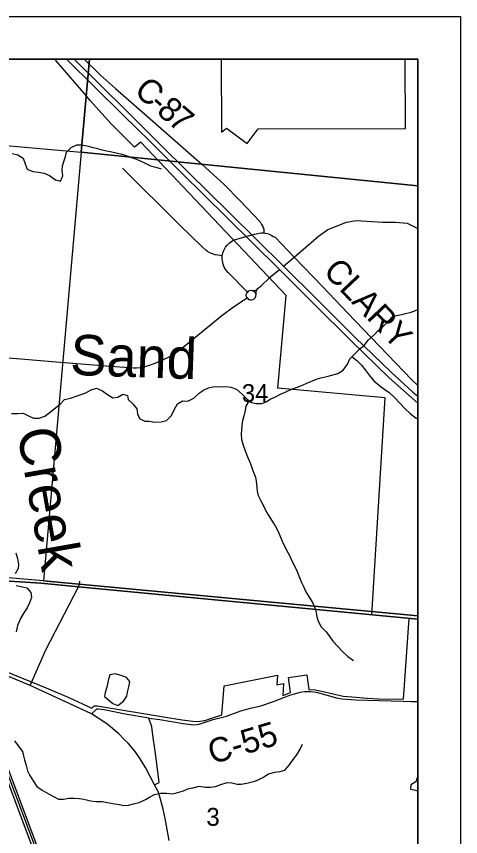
# Model space of a CAD drawing. Extents: x 0 to 34, y 0 to 22.
# Drawn here: x 29.378 to 30.417, y 19.082 to 21 of the extents above; entities that cross this region are included whole.
import ezdxf

# ---------------------------------------------------------------- set-up
doc = ezdxf.new("R2010")
doc.units = 0
for name, color, linetype in [('GM_X_City_Street', 7, 'Continuous'), ('GM_X_Corporation', 7, 'Continuous'), ('GM_X_County_Road', 7, 'Continuous'), ('GM_X_County_Road_Text', 7, 'Continuous'), ('GM_X_Major_River', 7, 'Continuous'), ('GM_X_Major_River_Text', 7, 'Continuous'), ('GM_X_Minor_Lake', 7, 'Continuous'), ('GM_X_Minor_River', 7, 'Continuous'), ('GM_X_Minor_River_Text', 7, 'Continuous'), ('GM_X_Rail_Line', 7, 'Continuous'), ('GM_X_Section_Text', 7, 'Continuous'), ('GM_X_State_Route', 7, 'Continuous'), ('GM_X_Township_Road', 7, 'Continuous'), ('GM_X_US_Route', 7, 'Continuous'), ('SH_Data', 7, 'Continuous')]:
    doc.layers.add(name, color=color, linetype=linetype)

msp = doc.modelspace()

# ---------------------------------------------------------------- linework, layer by layer
at = {"layer": 'GM_X_City_Street'}
for points in [[(29.8594, 20.44), (29.8487, 20.4415), (29.8428, 20.4426), (29.8363, 20.4448), (29.8299, 20.4469), (29.8248, 20.4502), (29.8206, 20.4536), (29.812, 20.4612), (29.7604, 20.5117), (29.6261, 20.645)], [(29.9382, 20.3499), (29.937, 20.3526), (29.9356, 20.3546), (29.9343, 20.3563), (29.9301, 20.358), (29.9275, 20.3588), (29.923, 20.3583), (29.9197, 20.3573), (29.9179, 20.3553), (29.873, 20.4009), (29.8673, 20.4073), (29.8639, 20.414), (29.8614, 20.421), (29.8595, 20.4288), (29.8592, 20.4334), (29.8594, 20.44)], [(29.9177, 20.3417), (29.9162, 20.3446), (29.9154, 20.3476), (29.9154, 20.3501), (29.9166, 20.3529), (29.9179, 20.3553)], [(29.9177, 20.3417), (29.921, 20.3384), (29.9243, 20.3371), (29.9274, 20.3371), (29.931, 20.3378), (29.9341, 20.3393), (29.9364, 20.3421), (29.9377, 20.3458), (29.9382, 20.3499)], [(28.95, 20.2316), (29.0526, 20.2256), (29.1647, 20.2167), (29.2757, 20.2079), (29.3882, 20.1992), (29.48, 20.1917), (29.5875, 20.1831), (29.6516, 20.1783), (29.6584, 20.1781), (29.6681, 20.179), (29.6791, 20.1815), (29.6912, 20.1852), (29.7063, 20.1906), (29.722, 20.1978), (29.7365, 20.205), (29.7592, 20.2196), (29.858, 20.3004), (29.8857, 20.3208), (29.9177, 20.3417)]]:
    msp.add_lwpolyline(points, dxfattribs=at)
at = {"layer": 'GM_X_Corporation'}
for points in [[(27.713, 19.8126), (27.7479, 19.8098), (27.921, 19.7976), (28.0078, 19.7898), (28.15, 19.7813), (28.3845, 19.7702), (28.4743, 19.7657), (28.6835, 19.7478), (28.7311, 19.743), (28.8977, 19.7297), (28.9889, 19.7198), (29.3495, 19.6807), (29.4353, 19.675), (29.5232, 19.6666), (30.3167, 19.5906), (30.3167, 20.9), (26.3743, 20.9)], [(29.5806, 18.6469), (29.2591, 19.5062), (29.4529, 19.4276), (29.5007, 19.4078), (29.5541, 19.3823), (29.5597, 19.3879), (29.5664, 19.3884), (29.731, 19.3604), (29.7656, 19.3552), (29.7905, 19.3521), (29.8008, 19.3516), (29.8187, 19.354), (29.8585, 19.3674), (29.8636, 19.4347), (29.9887, 19.4598), (29.9872, 19.4371), (30.0026, 19.4402), (30.001, 19.4124), (30.0189, 19.419), (30.0139, 19.4545), (30.0571, 19.4606), (30.0619, 19.4264), (30.0769, 19.4252), (30.0952, 19.4213), (30.1144, 19.4168), (30.142, 19.411), (30.1621, 19.4088), (30.1987, 19.4063), (30.2247, 19.4047), (30.2833, 19.4038), (30.2961, 19.5924), (30.2089, 19.6008), (30.2405, 20.1082), (29.9891, 20.1305), (30.0087, 20.3472), (29.6686, 20.7058), (29.6541, 20.6939), (29.6372, 20.7116), (29.5983, 20.7499), (29.5502, 20.8033), (29.5299, 20.8277), (29.4707, 20.8964), (29.467, 20.9), (29.0005, 20.9)], [(30.3167, 14.1), (30.3167, 19.5906), (29.5232, 19.6666), (29.4353, 19.675), (29.3495, 19.6807), (28.9889, 19.7198), (28.8977, 19.7297), (28.7311, 19.743), (28.6835, 19.7478), (28.4743, 19.7657), (28.3845, 19.7702), (28.15, 19.7813), (28.0078, 19.7898), (27.921, 19.7976), (27.7479, 19.8098), (27.713, 19.8126)], [(29.2436, 19.5128), (29.5681, 18.6478)]]:
    msp.add_lwpolyline(points, dxfattribs=at)
for points in [[(29.5485, 20.9), (28.5537, 20.9), (28.5465, 20.7695), (29.5293, 20.6826)], [(30.3167, 20.6035), (30.3167, 20.9), (29.5485, 20.9), (29.5293, 20.6826)], [(30.2871, 20.9), (29.857, 20.9), (29.8577, 20.7293), (29.8692, 20.7387), (29.9178, 20.7025), (29.9435, 20.737), (30.2878, 20.7383)], [(28.5465, 20.7695), (29.5293, 20.6826), (29.4415, 19.6802), (29.3585, 19.6871), (28.4917, 19.7627)], [(30.3167, 19.5984), (30.3167, 20.6035), (29.5293, 20.6826), (29.4415, 19.6802)], [(30.3167, 18.7853), (30.3167, 19.5984), (29.4415, 19.6802), (29.3585, 19.6871), (29.2972, 18.6715), (30.2969, 18.5954)]]:
    msp.add_lwpolyline(points, close=True, dxfattribs=at)
at = {"layer": 'GM_X_County_Road'}
for points in [[(29.5366, 20.9), (29.5747, 20.8628), (29.6097, 20.8311), (29.6843, 20.7659), (29.8124, 20.6539), (29.864, 20.607), (29.9002, 20.5693)], [(29.9002, 20.5693), (29.9476, 20.52), (29.9498, 20.5166), (29.9513, 20.5138), (29.9528, 20.5111), (29.9539, 20.5085), (29.9553, 20.5051), (29.9562, 20.5023), (29.9568, 20.4979), (29.9563, 20.4936)], [(30.1029, 20.4992), (30.1062, 20.5014), (30.1237, 20.5088), (30.1497, 20.519), (30.1728, 20.5227), (30.2349, 20.519), (30.2643, 20.5192), (30.2914, 20.5162), (30.3167, 20.5038)], [(29.8858, 20.4766), (29.8879, 20.4777), (29.9143, 20.4855), (29.9289, 20.489), (29.9347, 20.4905)], [(29.9347, 20.4905), (29.9465, 20.4935), (29.9502, 20.4938), (29.9563, 20.4936)], [(29.9563, 20.4936), (29.9591, 20.4934), (29.9653, 20.4922), (29.969, 20.4908), (29.975, 20.4877), (29.9784, 20.4856), (29.9826, 20.4836), (30.0273, 20.437)], [(30.0028, 20.4163), (30.0273, 20.437), (30.0663, 20.4708), (30.084, 20.4864), (30.1029, 20.4992)], [(29.8594, 20.44), (29.8605, 20.4461), (29.8623, 20.4509), (29.8641, 20.4557), (29.8671, 20.4603), (29.8708, 20.4652), (29.8759, 20.4705), (29.882, 20.4747), (29.8858, 20.4766)], [(30.0273, 20.437), (30.0934, 20.3682), (30.1518, 20.3071), (30.3027, 20.1503), (30.3167, 20.1367)], [(29.9686, 20.3878), (29.9693, 20.3884), (29.993, 20.408)], [(29.9382, 20.3499), (29.9382, 20.3534), (29.9389, 20.357), (29.9402, 20.3605), (29.9435, 20.3643), (29.9509, 20.3705), (29.9686, 20.3878)], [(29.9402, 20.3605), (29.9373, 20.3593), (29.9348, 20.3587), (29.9301, 20.358)], [(29.6878, 19.3589), (29.7135, 19.3561), (29.7681, 19.3467), (29.793, 19.3433), (29.8056, 19.345), (29.8382, 19.356), (29.8689, 19.3638), (29.9029, 19.376), (29.9252, 19.3825), (29.9497, 19.388), (29.9792, 19.398), (30.0176, 19.4129), (30.0412, 19.42), (30.0519, 19.4216), (30.0658, 19.4213), (30.0787, 19.4197), (30.1013, 19.4139), (30.1263, 19.4066), (30.1393, 19.4045), (30.1712, 19.4021), (30.2821, 19.3986)], [(30.2821, 19.3986), (30.3021, 19.398), (30.3167, 19.3984)], [(29.6878, 19.3589), (29.632, 19.3687), (29.5827, 19.3787), (29.5687, 19.3806), (29.5653, 19.38), (29.5538, 19.3697)], [(29.7011, 19.2033), (29.7114, 19.2092), (29.7105, 19.2223), (29.7077, 19.2401), (29.7024, 19.2822), (29.6971, 19.3198), (29.6942, 19.3388), (29.6878, 19.3589)]]:
    msp.add_lwpolyline(points, dxfattribs=at)
at = {"layer": 'GM_X_Major_River'}
for points in [[(29.3768, 19.7455), (29.3801, 19.7329), (29.3827, 19.7188), (29.3818, 19.7094), (29.3753, 19.6965)], [(29.377, 19.6696), (29.3883, 19.6672), (29.4023, 19.6641), (29.4117, 19.653), (29.4131, 19.6416), (29.4085, 19.6287), (29.4027, 19.6174), (29.3954, 19.6053), (29.3873, 19.5925), (29.3803, 19.5762), (29.3776, 19.5614)]]:
    msp.add_lwpolyline(points, dxfattribs=at)
at = {"layer": 'GM_X_Minor_Lake'}
for points in [[(29.614, 19.4614), (29.6097, 19.4626), (29.5964, 19.4607), (29.5922, 19.4475), (29.5891, 19.4319), (29.5857, 19.4194), (29.5838, 19.4099)], [(29.5838, 19.4099), (29.6034, 19.3936), (29.6151, 19.3886), (29.6284, 19.3988), (29.636, 19.4109), (29.6379, 19.4204), (29.641, 19.4325), (29.6429, 19.4446), (29.635, 19.4545), (29.6225, 19.4591), (29.614, 19.4614)], [(30.3167, 19.2305), (30.3162, 19.2224), (30.3116, 19.2107), (30.3006, 19.2035), (30.2998, 19.1936), (30.3081, 19.1916)], [(30.3081, 19.1916), (30.3138, 19.1902), (30.3167, 19.189)]]:
    msp.add_lwpolyline(points, dxfattribs=at)
at = {"layer": 'GM_X_Minor_River'}
for points in [[(29.3682, 20.6796), (29.3815, 20.6765), (29.3939, 20.6685), (29.3984, 20.6552), (29.4033, 20.6427), (29.4165, 20.6373), (29.4294, 20.6361), (29.443, 20.6334), (29.4555, 20.6284), (29.4695, 20.6182), (29.4812, 20.6151), (29.4865, 20.6276), (29.4847, 20.6397), (29.4855, 20.6503), (29.4885, 20.6606), (29.4923, 20.6727), (29.495, 20.6822), (29.506, 20.6931), (29.5189, 20.6999), (29.5295, 20.6999), (29.5424, 20.6972), (29.5541, 20.6945), (29.5643, 20.6922), (29.5753, 20.6891), (29.5851, 20.6868), (29.601, 20.6833), (29.6112, 20.681), (29.6241, 20.6776), (29.6343, 20.6749), (29.6441, 20.6707), (29.6543, 20.6676), (29.6656, 20.6634), (29.6789, 20.6569), (29.6913, 20.6508), (29.7042, 20.6477), (29.7167, 20.6435)], [(29.3665, 20.0713), (29.3802, 20.0712), (29.3934, 20.0727), (29.4059, 20.0658), (29.418, 20.0605), (29.4312, 20.0608), (29.4445, 20.0657), (29.454, 20.0721), (29.4665, 20.0823), (29.4798, 20.0933), (29.49, 20.1046), (29.504, 20.1076), (29.5173, 20.1117), (29.5294, 20.1159), (29.54, 20.1196), (29.5525, 20.1268), (29.5654, 20.1305), (29.579, 20.1244), (29.5888, 20.1172), (29.6036, 20.1084), (29.6153, 20.1095), (29.6271, 20.1167), (29.6377, 20.1136), (29.6391, 20.1041), (29.6501, 20.0942), (29.6591, 20.0828), (29.661, 20.0711), (29.6659, 20.0597), (29.6779, 20.0539), (29.6882, 20.0539), (29.7014, 20.0512), (29.7162, 20.0519), (29.729, 20.0549), (29.7404, 20.067), (29.7465, 20.0802), (29.7545, 20.0939), (29.7663, 20.1014), (29.7784, 20.1006), (29.7928, 20.1074), (29.8061, 20.1199), (29.8156, 20.1259), (29.8273, 20.1319), (29.841, 20.1345), (29.8542, 20.1337), (29.8693, 20.1344), (29.8796, 20.1329), (29.8928, 20.1283), (29.9056, 20.1165), (29.9177, 20.1051), (29.9279, 20.0975), (29.9388, 20.0948), (29.9521, 20.0947), (29.9619, 20.0985), (29.9729, 20.1056), (29.9824, 20.1098), (29.9957, 20.1169), (30.0067, 20.1218), (30.0211, 20.1286), (30.0332, 20.1327), (30.0468, 20.138), (30.0567, 20.1425), (30.0794, 20.1516), (30.0897, 20.1546), (30.1037, 20.1579), (30.1158, 20.1613), (30.1294, 20.1647), (30.142, 20.173), (30.1522, 20.1866), (30.1579, 20.1994), (30.1701, 20.2115), (30.1819, 20.2233), (30.1914, 20.2308), (30.2012, 20.2437), (30.2142, 20.2558), (30.224, 20.2656), (30.2335, 20.2728), (30.2438, 20.2837), (30.2563, 20.2977), (30.2665, 20.3007), (30.2783, 20.3033), (30.2881, 20.3056), (30.301, 20.3086), (30.3108, 20.3127), (30.3167, 20.3146)], [(30.1627, 20.2042), (30.1738, 20.1952), (30.1851, 20.1849), (30.1938, 20.1739), (30.2025, 20.161), (30.2134, 20.1481), (30.2274, 20.1366), (30.2394, 20.1275), (30.2493, 20.1206), (30.2617, 20.1088), (30.2749, 20.0955), (30.2874, 20.0826), (30.2987, 20.0712), (30.3126, 20.0609), (30.3167, 20.0604)], [(29.9223, 20.1016), (29.9146, 20.0888), (29.913, 20.0785), (29.91, 20.0653), (29.9069, 20.0551), (29.9054, 20.0433), (29.9046, 20.0334), (29.9038, 20.0232), (29.9041, 20.0107), (29.9079, 19.9978), (29.9127, 19.9841), (29.918, 19.9701), (29.9236, 19.9575), (29.9277, 19.9473), (29.9319, 19.9363), (29.9367, 19.9226), (29.9386, 19.9131), (29.9401, 19.8995), (29.9412, 19.8896), (29.9434, 19.8797), (29.949, 19.8687), (29.9551, 19.8573), (29.9607, 19.8459), (29.9667, 19.8349), (29.9761, 19.8197), (29.9833, 19.8087), (29.9889, 19.7973), (29.9938, 19.7866), (29.9994, 19.773), (30.0066, 19.7582), (30.0126, 19.7468), (30.0178, 19.7365), (30.0231, 19.7255), (30.0295, 19.7122), (30.0348, 19.7019), (30.04, 19.6879), (30.0449, 19.6761), (30.0502, 19.6655), (30.055, 19.6548), (30.0637, 19.64), (30.0712, 19.6279), (30.0765, 19.6157), (30.0787, 19.6062), (30.0806, 19.596), (30.0839, 19.5861), (30.0903, 19.5728), (30.1024, 19.561), (30.1111, 19.5492), (30.1175, 19.539), (30.1307, 19.526), (30.1397, 19.5161), (30.1533, 19.5036), (30.1661, 19.4941)], [(29.3734, 19.3064), (29.3817, 19.2946), (29.3918, 19.2813), (29.3944, 19.2714), (29.3971, 19.2615), (29.4004, 19.2482), (29.4038, 19.2357), (29.4094, 19.2251), (29.417, 19.2125), (29.4252, 19.1992), (29.4384, 19.1909), (29.4543, 19.1813), (29.4645, 19.1764), (29.4766, 19.1702), (29.488, 19.1698), (29.5008, 19.1721), (29.5126, 19.1724), (29.5243, 19.1712), (29.5353, 19.1697), (29.5511, 19.1658), (29.5644, 19.1643), (29.578, 19.1642), (29.5912, 19.1619), (29.6033, 19.1596), (29.6185, 19.1573), (29.6287, 19.1549), (29.6397, 19.156), (29.6514, 19.159), (29.6647, 19.162), (29.6795, 19.1692), (29.6889, 19.1748), (29.7011, 19.1809), (29.7147, 19.1839), (29.7291, 19.1842), (29.7427, 19.1826), (29.7525, 19.1849), (29.7685, 19.1897), (29.7791, 19.1943), (29.7901, 19.1961), (29.8052, 19.1999), (29.82, 19.1979), (29.8313, 19.1979), (29.8434, 19.1993), (29.8559, 19.2042), (29.8707, 19.2087), (29.8813, 19.2083), (29.8938, 19.2049), (29.9036, 19.2052), (29.9169, 19.2074), (29.9354, 19.2119), (29.9449, 19.2161), (29.9544, 19.2206), (29.9673, 19.2293), (29.9821, 19.2326), (29.9949, 19.2345), (30.0059, 19.2379), (30.0162, 19.25), (30.0253, 19.2624), (30.0333, 19.2734), (30.0417, 19.2867), (30.047, 19.2984)]]:
    msp.add_lwpolyline(points, dxfattribs=at)
at = {"layer": 'GM_X_Rail_Line'}
msp.add_lwpolyline([(29.4527, 18.9755), (29.2926, 19.4017), (29.1913, 19.6716)], dxfattribs=at)
at = {"layer": 'GM_X_State_Route'}
for points in [[(29.4998, 19.3943), (29.4097, 19.4354), (29.3673, 19.4536), (29.2078, 19.5211), (29.0317, 19.5955), (29.0273, 19.5976)], [(29.5867, 19.3476), (29.5538, 19.3697), (29.4998, 19.3943)], [(29.6305, 19.3089), (29.6172, 19.3224), (29.5883, 19.3464), (29.5867, 19.3476)], [(29.7213, 19.1468), (29.7147, 19.1697), (29.709, 19.1877), (29.7011, 19.2033), (29.6904, 19.2229), (29.6797, 19.244), (29.667, 19.2641), (29.6553, 19.2816), (29.6388, 19.3004), (29.6305, 19.3089)], [(29.7349, 19.0729), (29.7257, 19.1248), (29.7213, 19.1468)]]:
    msp.add_lwpolyline(points, dxfattribs=at)
at = {"layer": 'GM_X_Township_Road'}
msp.add_lwpolyline([(29.4097, 19.4354), (29.4467, 19.5189), (29.5234, 19.666), (29.5256, 19.6729), (29.5261, 19.6799)], dxfattribs=at)
at = {"layer": 'GM_X_US_Route'}
for points in [[(29.4946, 20.9), (29.6275, 20.7692), (29.6908, 20.7072), (29.7386, 20.6593)], [(29.5127, 20.9), (29.6343, 20.7797), (29.7147, 20.6997), (29.7794, 20.6362), (29.8764, 20.5406), (30.0028, 20.4163)], [(29.7386, 20.6593), (29.764, 20.634), (29.8688, 20.5304), (29.993, 20.408)], [(29.993, 20.408), (30.0725, 20.3289), (30.1612, 20.2405), (30.2496, 20.1552), (30.2964, 20.1134), (30.3167, 20.0957)], [(30.0028, 20.4163), (30.0807, 20.3388), (30.1694, 20.2504), (30.2547, 20.1678), (30.3047, 20.1218), (30.3167, 20.1119)]]:
    msp.add_lwpolyline(points, dxfattribs=at)
at = {"layer": 'SH_Data'}
for points in [[(23.4167, 21), (30.4167, 21), (30.4167, 14), (23.4167, 14)], [(23.5167, 20.9), (30.3167, 20.9), (30.3167, 14.1), (23.5167, 14.1)]]:
    msp.add_lwpolyline(points, close=True, dxfattribs=at)

# ---------------------------------------------------------------- texts
at = {"layer": 'GM_X_County_Road_Text'}
for s, height, rotation, p in [('C', 0.0568, 317.823, (29.6504, 20.8223)), ('-', 0.0568, 318.5269, (29.6853, 20.7907)), ('8', 0.0568, 319.126, (29.7031, 20.7749)), ('7', 0.0568, 319.5366, (29.7297, 20.7519)), ('CLARY', 0.05682, 313.4367, (30.093, 20.4019)), ('C-55', 0.05682, 16.6987, (29.8358, 19.2511))]:
    msp.add_text(s, height=height, rotation=rotation, dxfattribs=at).set_placement(p)
at = {"layer": 'GM_X_Major_River_Text'}
msp.add_text('Creek', height=0.09471, rotation=279.999, dxfattribs=at).set_placement((29.3791, 20.0316))
at = {"layer": 'GM_X_Minor_River_Text'}
msp.add_text('Sand', height=0.0947, rotation=357.9973, dxfattribs=at).set_placement((29.5027, 20.162))
at = {"layer": 'GM_X_Section_Text'}
for s, height, p in [('34', 0.04186, (29.905, 20.0984)), ('3', 0.0419, (29.8221, 19.1076))]:
    msp.add_text(s, height=height, rotation=0, dxfattribs=at).set_placement(p)

doc.saveas('drawing.dxf')
